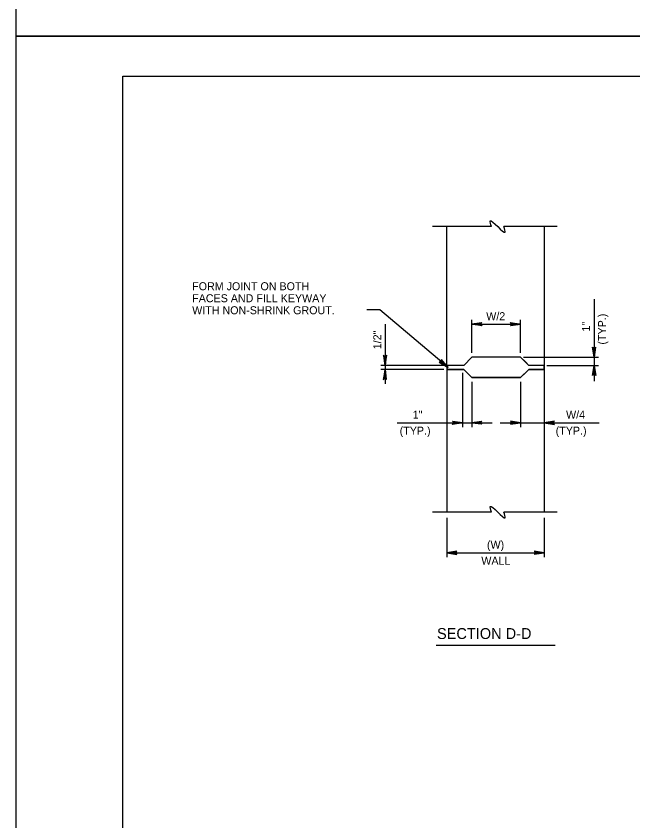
# Model space of a CAD drawing. Extents: x 641328 to 643024, y 298283 to 300065.
# Drawn here: x 641327.5 to 641559, y 298583 to 298884.8 of the extents above; entities that cross this region are included whole.
import ezdxf

# ---------------------------------------------------------------- set-up
doc = ezdxf.new("R2010")
doc.units = 0
for name, color, linetype in [('2', 7, 'Continuous'), ('Default', 7, 'Continuous'), ('PLT-BNDY', 7, 'Continuous')]:
    doc.layers.add(name, color=color, linetype=linetype)

msp = doc.modelspace()

# ---------------------------------------------------------------- linework, layer by layer
at = {"layer": '2'}
for p, q in [((641367.51, 298298.3), (641367.51, 298862.3)), ((641367.51, 298862.3), (642153.5, 298862.3)), ((641505.91, 298805.87), (641483.78, 298805.87)), ((641489.14, 298753.84), (641489.14, 298805.87)), ((641530.57, 298805.87), (641510.54, 298805.87)), ((641525.71, 298805.87), (641525.71, 298753.84)), ((641544.36, 298778.67), (641544.36, 298756.89)), ((641463.98, 298774.71), (641459.16, 298774.71)), ((641489.58, 298753.08), (641463.98, 298774.71)), ((641498.5, 298758.49), (641498.5, 298770.91)), ((641516.79, 298758.49), (641516.79, 298770.91)), ((641465.94, 298769.29), (641465.94, 298746.95)), ((641498.5, 298769.28), (641502.29, 298769.92)), ((641502.1, 298769.74), (641498.5, 298769.28)), ((641498.5, 298769.28), (641501.97, 298769.48)), ((641498.5, 298769.28), (641501.97, 298769.3)), ((641498.5, 298769.28), (641516.79, 298769.28)), ((641501.97, 298769.12), (641498.5, 298769.28)), ((641498.5, 298769.28), (641502.11, 298768.85)), ((641502.3, 298768.69), (641498.5, 298769.28)), ((641501.97, 298769.48), (641502.1, 298769.74)), ((641501.97, 298769.12), (641501.97, 298769.48)), ((641502.11, 298768.85), (641501.97, 298769.12)), ((641502.29, 298769.92), (641502.1, 298769.74)), ((641502.11, 298768.85), (641502.3, 298768.69)), ((641513.18, 298769.71), (641512.99, 298769.87)), ((641512.99, 298769.87), (641516.79, 298769.28)), ((641516.79, 298769.28), (641512.99, 298768.65)), ((641512.99, 298768.65), (641513.19, 298768.82)), ((641513.18, 298769.71), (641513.31, 298769.45)), ((641516.79, 298769.28), (641513.18, 298769.71)), ((641513.19, 298768.82), (641516.79, 298769.28)), ((641513.32, 298769.09), (641513.19, 298768.82)), ((641513.31, 298769.45), (641516.79, 298769.28)), ((641513.31, 298769.45), (641513.32, 298769.09)), ((641516.79, 298769.28), (641513.32, 298769.09)), ((641516.79, 298769.28), (641513.32, 298769.27)), ((641544.36, 298756.89), (641543.73, 298760.69)), ((641543.73, 298760.69), (641543.9, 298760.49)), ((641544.17, 298760.36), (641543.9, 298760.49)), ((641543.9, 298760.49), (641544.36, 298756.89)), ((641544.53, 298760.37), (641544.17, 298760.36)), ((641544.36, 298756.89), (641544.17, 298760.36)), ((641544.36, 298756.89), (641544.35, 298760.37)), ((641544.95, 298760.69), (641544.36, 298756.89)), ((641544.36, 298756.89), (641544.79, 298760.5)), ((641544.53, 298760.37), (641544.36, 298756.89)), ((641544.79, 298760.5), (641544.53, 298760.37)), ((641544.79, 298760.5), (641544.95, 298760.69)), ((641465.51, 298757.45), (641465.35, 298757.65)), ((641465.35, 298757.65), (641465.94, 298753.84)), ((641465.51, 298757.45), (641465.77, 298757.32)), ((641465.94, 298753.84), (641465.51, 298757.45)), ((641465.77, 298757.32), (641465.94, 298753.84)), ((641465.77, 298757.32), (641466.13, 298757.32)), ((641465.94, 298753.84), (641466.57, 298757.64)), ((641466.4, 298757.44), (641465.94, 298753.84)), ((641465.94, 298753.84), (641466.13, 298757.32)), ((641465.94, 298753.84), (641465.95, 298757.32)), ((641466.13, 298757.32), (641466.4, 298757.44)), ((641466.57, 298757.64), (641466.4, 298757.44)), ((641487.05, 298755.47), (641487.12, 298755.76)), ((641489.58, 298753.08), (641487.09, 298756.02)), ((641487.09, 298756.02), (641487.12, 298755.76)), ((641487.12, 298755.76), (641489.58, 298753.08)), ((641498.5, 298756.89), (641495.45, 298753.84)), ((641516.79, 298756.89), (641498.5, 298756.89)), ((641518.59, 298755.1), (641516.79, 298756.89)), ((641517.94, 298756.89), (641545.99, 298756.89)), ((641544.36, 298756.89), (641544.36, 298747.97)), ((641487.99, 298753.84), (641464.31, 298753.84)), ((641486.54, 298755.08), (641486.29, 298755.09)), ((641486.29, 298755.09), (641489.58, 298753.08)), ((641486.54, 298755.08), (641486.82, 298755.2)), ((641489.58, 298753.08), (641486.54, 298755.08)), ((641486.82, 298755.2), (641487.05, 298755.47)), ((641486.82, 298755.2), (641489.58, 298753.08)), ((641489.58, 298753.08), (641486.93, 298755.34)), ((641489.58, 298753.08), (641487.05, 298755.47)), ((641495.45, 298753.84), (641489.14, 298753.84)), ((641489.14, 298753.84), (641489.14, 298752.32)), ((641495.45, 298753.84), (641489.14, 298753.84)), ((641489.14, 298753.84), (641489.14, 298752.32)), ((641519.84, 298753.84), (641518.59, 298755.1)), ((641519.84, 298753.84), (641518.59, 298755.1)), ((641525.71, 298753.84), (641519.84, 298753.84)), ((641525.71, 298753.84), (641519.84, 298753.84)), ((641525.71, 298753.84), (641525.71, 298752.32)), ((641526.69, 298753.84), (641545.99, 298753.84)), ((641543.77, 298750.04), (641544.36, 298753.84)), ((641544.36, 298753.84), (641543.93, 298750.24)), ((641544.2, 298750.37), (641544.36, 298753.84)), ((641544.36, 298753.84), (641544.56, 298750.37)), ((641544.82, 298750.25), (641544.36, 298753.84)), ((641544.36, 298753.84), (641545, 298750.05)), ((641544.36, 298753.84), (641544.38, 298750.37)), ((641487.99, 298752.32), (641464.31, 298752.32)), ((641465.94, 298752.32), (641465.3, 298748.53)), ((641465.48, 298748.72), (641465.94, 298752.32)), ((641465.94, 298752.32), (641465.74, 298748.85)), ((641465.94, 298752.32), (641465.92, 298748.85)), ((641466.1, 298748.85), (641465.94, 298752.32)), ((641465.94, 298752.32), (641466.37, 298748.71)), ((641466.53, 298748.52), (641465.94, 298752.32)), ((641495.45, 298752.32), (641489.14, 298752.32)), ((641489.14, 298752.32), (641489.14, 298698.82)), ((641489.14, 298752.32), (641495.45, 298752.32)), ((641495.01, 298750.99), (641495.01, 298730.71)), ((641495.45, 298752.32), (641498.5, 298749.27)), ((641519.84, 298752.32), (641518.59, 298751.07)), ((641525.71, 298752.32), (641519.84, 298752.32)), ((641519.84, 298752.32), (641525.71, 298752.32)), ((641525.71, 298752.32), (641525.71, 298698.82)), ((641543.93, 298750.24), (641543.77, 298750.04)), ((641543.93, 298750.24), (641544.2, 298750.37)), ((641544.2, 298750.37), (641544.56, 298750.37)), ((641544.56, 298750.37), (641544.82, 298750.25)), ((641545, 298750.05), (641544.82, 298750.25)), ((641465.3, 298748.53), (641465.48, 298748.72)), ((641465.74, 298748.85), (641465.48, 298748.72)), ((641466.1, 298748.85), (641465.74, 298748.85)), ((641466.37, 298748.71), (641466.1, 298748.85)), ((641466.37, 298748.71), (641466.53, 298748.52)), ((641498.5, 298749.27), (641516.79, 298749.27)), ((641498.5, 298747.68), (641498.5, 298730.71)), ((641516.79, 298747.68), (641516.79, 298730.71)), ((641470.46, 298732.34), (641506.15, 298732.34)), ((641491.4, 298732.77), (641491.21, 298732.93)), ((641491.21, 298732.93), (641495.01, 298732.34)), ((641495.01, 298732.34), (641491.22, 298731.7)), ((641491.22, 298731.7), (641491.41, 298731.88)), ((641491.4, 298732.77), (641491.54, 298732.5)), ((641495.01, 298732.34), (641491.4, 298732.77)), ((641491.41, 298731.88), (641495.01, 298732.34)), ((641491.54, 298732.14), (641491.41, 298731.88)), ((641491.54, 298732.5), (641495.01, 298732.34)), ((641491.54, 298732.5), (641491.54, 298732.14)), ((641495.01, 298732.34), (641491.54, 298732.14)), ((641495.01, 298732.34), (641491.54, 298732.32)), ((641498.5, 298732.34), (641502.29, 298732.97)), ((641502.1, 298732.8), (641498.5, 298732.34)), ((641498.5, 298732.34), (641501.97, 298732.53)), ((641498.5, 298732.34), (641501.97, 298732.35)), ((641501.97, 298732.17), (641498.5, 298732.34)), ((641498.5, 298732.34), (641502.11, 298731.91)), ((641502.3, 298731.75), (641498.5, 298732.34)), ((641501.97, 298732.53), (641502.1, 298732.8)), ((641501.97, 298732.17), (641501.97, 298732.53)), ((641502.11, 298731.91), (641501.97, 298732.17)), ((641502.29, 298732.97), (641502.1, 298732.8)), ((641502.11, 298731.91), (641502.3, 298731.75)), ((641509.2, 298732.34), (641525.71, 298732.34)), ((641516.79, 298732.34), (641512.99, 298732.97)), ((641512.99, 298732.97), (641513.19, 298732.8)), ((641512.99, 298731.75), (641516.79, 298732.34)), ((641513.18, 298731.91), (641512.99, 298731.75)), ((641516.79, 298732.34), (641513.18, 298731.91)), ((641513.18, 298731.91), (641513.31, 298732.17)), ((641513.32, 298732.53), (641513.19, 298732.8)), ((641513.19, 298732.8), (641516.79, 298732.34)), ((641513.31, 298732.17), (641513.32, 298732.53)), ((641513.31, 298732.17), (641516.79, 298732.34)), ((641516.79, 298732.34), (641513.32, 298732.53)), ((641516.79, 298732.34), (641513.32, 298732.35)), ((641529.51, 298732.93), (641525.71, 298732.34)), ((641525.71, 298732.34), (641529.32, 298732.77)), ((641529.19, 298732.5), (641525.71, 298732.34)), ((641525.71, 298732.34), (641529.18, 298732.14)), ((641529.31, 298731.88), (641525.71, 298732.34)), ((641525.71, 298732.34), (641529.51, 298731.7)), ((641525.71, 298732.34), (641529.18, 298732.32)), ((641525.71, 298732.34), (641546.32, 298732.34)), ((641529.19, 298732.5), (641529.18, 298732.14)), ((641529.18, 298732.14), (641529.31, 298731.88)), ((641529.32, 298732.77), (641529.19, 298732.5)), ((641529.51, 298731.7), (641529.31, 298731.88)), ((641529.32, 298732.77), (641529.51, 298732.93)), ((641505.91, 298698.82), (641483.78, 298698.82)), ((641530.57, 298698.82), (641510.54, 298698.82)), ((641489.14, 298696.66), (641489.14, 298681.95)), ((641525.71, 298696.66), (641525.71, 298681.95)), ((641492.94, 298684.16), (641489.14, 298683.57)), ((641489.14, 298683.57), (641492.75, 298684)), ((641492.61, 298683.74), (641489.14, 298683.57)), ((641489.14, 298683.57), (641525.71, 298683.57)), ((641489.14, 298683.57), (641492.61, 298683.38)), ((641492.73, 298683.12), (641489.14, 298683.57)), ((641489.14, 298683.57), (641492.93, 298682.94)), ((641489.14, 298683.57), (641492.61, 298683.56)), ((641492.75, 298684), (641492.61, 298683.74)), ((641492.61, 298683.74), (641492.61, 298683.38)), ((641492.61, 298683.38), (641492.73, 298683.12)), ((641492.75, 298684), (641492.94, 298684.16)), ((641521.91, 298682.98), (641525.71, 298683.57)), ((641525.71, 298683.57), (641521.92, 298684.21)), ((641521.92, 298684.21), (641522.11, 298684.03)), ((641525.71, 298683.57), (641522.1, 298683.14)), ((641522.1, 298683.14), (641522.24, 298683.41)), ((641522.24, 298683.77), (641522.11, 298684.03)), ((641522.11, 298684.03), (641525.71, 298683.57)), ((641525.71, 298683.57), (641522.24, 298683.77)), ((641522.24, 298683.41), (641522.24, 298683.77)), ((641525.71, 298683.57), (641522.24, 298683.59)), ((641522.24, 298683.41), (641525.71, 298683.57)), ((641492.93, 298682.94), (641492.73, 298683.12)), ((641522.1, 298683.14), (641521.91, 298682.98))]:
    msp.add_line(p, q, dxfattribs=at)
for points in [[(641498.5, 298756.89), (641495.45, 298753.84)], [(641516.79, 298756.89), (641498.5, 298756.89)], [(641519.84, 298753.84), (641516.79, 298756.89)], [(641525.71, 298752.32), (641525.71, 298753.08), (641525.71, 298753.84)], [(641498.5, 298749.27), (641495.45, 298752.32)], [(641519.84, 298752.32), (641516.79, 298749.27)], [(641516.79, 298749.27), (641518.59, 298751.07), (641519.84, 298752.32)], [(641516.79, 298749.27), (641498.5, 298749.27)]]:
    msp.add_lwpolyline(points, dxfattribs=at)
for points in [[(641505.91, 298805.87), (641505.41, 298808), (641511.04, 298803.75), (641510.54, 298805.87)], [(641505.91, 298698.82), (641505.41, 298700.94), (641511.04, 298696.69), (641510.54, 298698.82)]]:
    msp.add_spline(points, degree=3, dxfattribs=at)
at = {"layer": 'Default'}
msp.add_line((641485.18, 298648.92), (641529.78, 298648.92), dxfattribs=at)
at = {"layer": 'PLT-BNDY'}
for points in [[(641327.51, 299471.3), (642168.51, 299471.3), (642168.51, 298877.3), (641327.51, 298877.3)], [(641327.51, 298877.3), (642168.51, 298877.3), (642168.51, 298283.3), (641327.51, 298283.3)]]:
    msp.add_lwpolyline(points, close=True, dxfattribs=at)

# ---------------------------------------------------------------- texts
at = {"layer": '2'}
for s, p in [('FORM JOINT ON BOTH', (641393.58, 298782)), ('FACES AND FILL KEYWAY', (641393.58, 298777.5)), ('WITH NON-SHRINK GROUT.', (641393.58, 298773))]:
    msp.add_text(s, height=3, dxfattribs=at).set_placement(p)
for s, rotation, p in [('W/2', 360, (641503.91, 298770.77)), ('(TYP.)', 90, (641548.86, 298761.63)), ('1"', 90, (641542.86, 298766.52)), ('1/2"', 90, (641464.53, 298759.87)), ('1"', 360, (641476.33, 298733.84)), ('W/4', 360, (641533.87, 298733.84)), ('(TYP.)', 360, (641471.44, 298727.84)), ('(TYP.)', 360, (641529.98, 298727.84)), ('(W)', 360, (641504.19, 298685.07)), ('WALL', 360, (641502.07, 298679.07))]:
    msp.add_text(s, height=3, rotation=rotation, dxfattribs=at).set_placement(p)
at = {"layer": 'Default'}
msp.add_text('SECTION D-D', height=4.08, dxfattribs=at).set_placement((641485.44, 298651.23))

doc.saveas('drawing.dxf')
